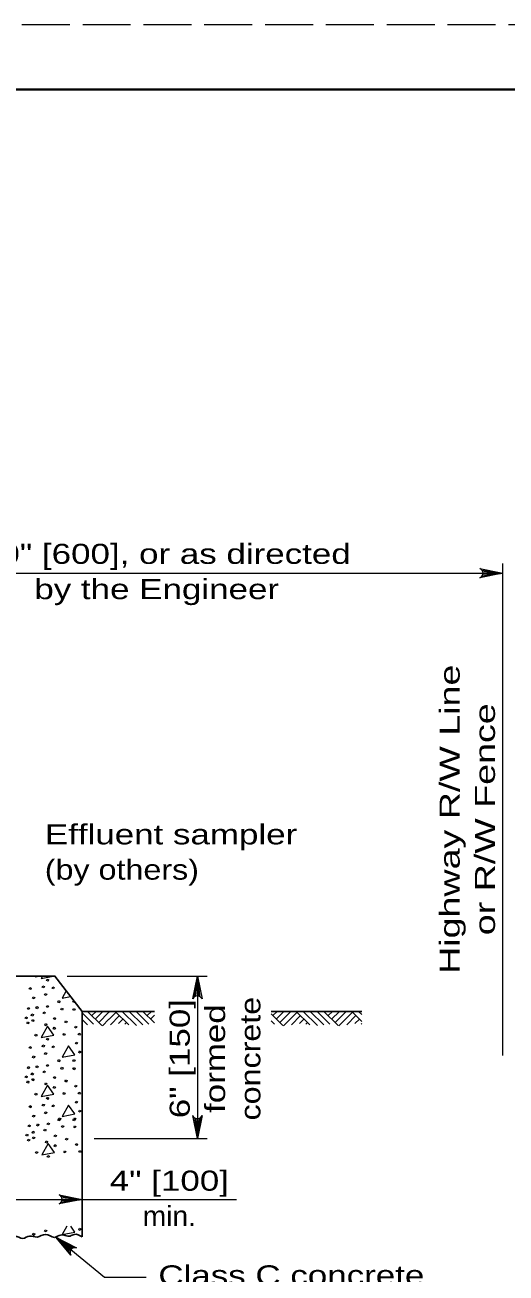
# Model space of a CAD drawing. Extents: x 1083.1 to 1117.1, y 719.4 to 741.4.
# Drawn here: x 1104.03 to 1107.77, y 731.66 to 741.35 of the extents above; entities that cross this region are included whole.
import ezdxf
from ezdxf.enums import TextEntityAlignment as Align

# ---------------------------------------------------------------- set-up
doc = ezdxf.new("R2010")
doc.units = 0
doc.header["$LTSCALE"] = 0.062
doc.linetypes.add('LONG_DASHED', pattern=[7.5, 6, -1.5])
doc.layers.add('1', color=7, linetype='Continuous', lineweight=13)

msp = doc.modelspace()

# ---------------------------------------------------------------- linework, layer by layer
at = {"layer": '1', "lineweight": 25}
for p, q in [((1085.12642, 740.85408), (1116.62642, 740.85408)), ((1105.03925, 733.6935), (1104.47725, 733.6935)), ((1106.63592, 733.6935), (1105.94508, 733.6935)), ((1106.64933, 733.6935), (1106.63592, 733.6935))]:
    msp.add_line(p, q, dxfattribs=at)
at = {"layer": '1'}
for p, q in [((1107.74417, 733.35042), (1107.74417, 737.17217)), ((1102.07067, 737.09617), (1107.74417, 737.09617)), ((1107.58108, 737.12117), (1107.74417, 737.09617)), ((1107.583, 737.07367), (1107.74417, 737.09617)), ((1107.58725, 737.11067), (1107.74417, 737.09617)), ((1107.58842, 737.08483), (1107.74417, 737.09617)), ((1107.59008, 737.09617), (1107.74417, 737.09617)), ((1104.36233, 733.96767), (1105.44883, 733.96767)), ((1105.348, 733.80458), (1105.37292, 733.96767)), ((1105.35842, 733.81075), (1105.37292, 733.96767)), ((1105.37292, 733.81367), (1105.37292, 733.96767)), ((1105.38425, 733.812), (1105.37292, 733.96767)), ((1105.39542, 733.8065), (1105.37292, 733.96767)), ((1104.41192, 733.77775), (1104.41317, 733.77725)), ((1104.47725, 733.68325), (1104.56525, 733.59533)), ((1104.52067, 733.6935), (1104.63067, 733.58358)), ((1104.52658, 733.68758), (1104.5325, 733.6935)), ((1104.55342, 733.66075), (1104.58617, 733.6935)), ((1104.58025, 733.63392), (1104.63992, 733.6935)), ((1104.58283, 733.6935), (1104.5835, 733.69292)), ((1104.60717, 733.60708), (1104.68658, 733.68658)), ((1104.68767, 733.68767), (1104.69358, 733.6935)), ((1104.68767, 733.63383), (1104.74142, 733.68758)), ((1104.69708, 733.58967), (1104.76825, 733.66075)), ((1104.7355, 733.6935), (1104.83967, 733.58942)), ((1104.78917, 733.6935), (1104.90008, 733.58267)), ((1104.84283, 733.6935), (1104.94833, 733.58808)), ((1104.89667, 733.6935), (1104.99492, 733.59533)), ((1104.95033, 733.6935), (1105.03925, 733.60467)), ((1104.95625, 733.68758), (1104.96217, 733.6935)), ((1104.98317, 733.66075), (1105.01592, 733.6935)), ((1105.01, 733.63392), (1105.03925, 733.66325)), ((1105.94508, 733.67408), (1106.03567, 733.58358)), ((1105.95842, 733.66075), (1105.99125, 733.6935)), ((1105.98525, 733.63392), (1106.04483, 733.6935)), ((1106.01208, 733.60708), (1106.09158, 733.68658)), ((1106.09267, 733.68767), (1106.0985, 733.6935)), ((1106.09267, 733.63383), (1106.1465, 733.68758)), ((1106.10217, 733.58967), (1106.17325, 733.66075)), ((1106.14042, 733.6935), (1106.24458, 733.58942)), ((1106.19417, 733.6935), (1106.305, 733.58267)), ((1106.24783, 733.6935), (1106.35342, 733.58808)), ((1106.30167, 733.6935), (1106.39992, 733.59533)), ((1106.35533, 733.6935), (1106.46533, 733.58358)), ((1106.36133, 733.68758), (1106.36725, 733.6935)), ((1106.38808, 733.66075), (1106.42092, 733.6935)), ((1106.41492, 733.63392), (1106.47458, 733.6935)), ((1106.44175, 733.60708), (1106.52133, 733.68658)), ((1106.52242, 733.68767), (1106.52825, 733.6935)), ((1106.52242, 733.63383), (1106.57617, 733.68758)), ((1106.53183, 733.58967), (1106.603, 733.66075)), ((1106.57017, 733.6935), (1106.64933, 733.61442)), ((1106.62383, 733.6935), (1106.64933, 733.66808)), ((1104.47725, 733.62992), (1104.48125, 733.63392)), ((1104.47725, 733.6295), (1104.51867, 733.58808)), ((1104.63625, 733.58233), (1104.68658, 733.63275)), ((1104.75967, 733.5985), (1104.79517, 733.63392)), ((1104.80942, 733.5945), (1104.822, 733.60708)), ((1105.03683, 733.60708), (1105.03925, 733.6095)), ((1105.94508, 733.62042), (1105.97017, 733.59533)), ((1106.04125, 733.58233), (1106.09158, 733.63275)), ((1106.16475, 733.5985), (1106.20008, 733.63392)), ((1106.21433, 733.5945), (1106.22692, 733.60708)), ((1106.47092, 733.58233), (1106.52133, 733.63275)), ((1106.59442, 733.5985), (1106.62975, 733.63392)), ((1106.644, 733.5945), (1106.64933, 733.59975)), ((1105.35033, 732.86808), (1105.37292, 732.70692)), ((1105.39783, 732.86992), (1105.37292, 732.70692)), ((1105.3615, 732.86258), (1105.37292, 732.70692)), ((1105.38742, 732.86375), (1105.37292, 732.70692)), ((1105.37292, 732.86092), (1105.37292, 732.70692)), ((1104.57217, 732.70692), (1105.44883, 732.70692)), ((1103.53142, 732.23342), (1105.67708, 732.23342)), ((1104.31417, 732.25833), (1104.47725, 732.23342)), ((1104.316, 732.21083), (1104.47725, 732.23342)), ((1104.32033, 732.24783), (1104.47725, 732.23342)), ((1104.3215, 732.222), (1104.47725, 732.23342)), ((1104.32317, 732.23342), (1104.47725, 732.23342)), ((1104.3935, 731.844), (1104.27367, 731.94075)), ((1104.38667, 731.83092), (1104.27367, 731.94075)), ((1104.38492, 731.819), (1104.27367, 731.94075)), ((1104.402, 731.85183), (1104.27367, 731.94075)), ((1104.41325, 731.85708), (1104.27367, 731.94075))]:
    msp.add_line(p, q, dxfattribs=at)
at = {"layer": '1', "linetype": 'LONG_DASHED'}
msp.add_lwpolyline([(1083.12642, 719.35408), (1117.12642, 719.35408), (1117.12642, 741.35408), (1083.12642, 741.35408)], close=True, dxfattribs=at)
at = {"layer": '1', "lineweight": 40}
msp.add_lwpolyline([(1085.12642, 740.85408), (1116.62642, 740.85408), (1116.62642, 719.85408), (1085.12642, 719.85408)], close=True, dxfattribs=at)
msp.add_lwpolyline([(1085.12642, 740.85408), (1116.62642, 740.85408), (1116.62642, 719.85408), (1085.12642, 719.85408)], close=True, dxfattribs=at)
at = {"layer": '1'}
for points in [[(1107.56617, 737.13183), (1107.74417, 737.09617), (1107.56617, 737.06058)], [(1104.12633, 733.96767), (1104.12233, 733.95967), (1104.1105, 733.96442), (1104.11217, 733.96767)], [(1104.1705, 733.96767), (1104.16033, 733.94942), (1104.254, 733.96767)], [(1105.33725, 733.78967), (1105.37292, 733.96767), (1105.4085, 733.78967)], [(1105.37292, 733.96767), (1105.37292, 733.56408), (1105.37292, 732.70692)], [(1104.35525, 733.85292), (1104.32333, 733.79592), (1104.38908, 733.80875)], [(1104.42092, 733.76708), (1104.41825, 733.76192), (1104.40642, 733.76667), (1104.41192, 733.77775)], [(1105.4085, 732.88492), (1105.37292, 732.70692), (1105.33725, 732.88492)], [(1104.29917, 732.269), (1104.47725, 732.23342), (1104.29917, 732.19775)], [(1104.359, 732.02417), (1104.32333, 731.96033), (1104.42067, 731.97925), (1104.38917, 732.02417)], [(1104.38983, 731.80125), (1104.27367, 731.94075), (1104.4345, 731.85667)], [(1104.27367, 731.94075), (1104.65108, 731.62875), (1104.97592, 731.62875)]]:
    msp.add_lwpolyline(points, dxfattribs=at)
at = {"layer": '1', "lineweight": 25}
for points in [[(1103.9085, 733.15417), (1103.94058, 733.96767), (1104.26742, 733.96767), (1104.47725, 733.6935)], [(1104.47725, 733.6935), (1104.47725, 732.02417), (1104.47725, 731.94125)]]:
    msp.add_lwpolyline(points, dxfattribs=at)
at = {"layer": '1'}
for points in [[(1104.20625, 733.94467), (1104.21808, 733.93992), (1104.21333, 733.928), (1104.2015, 733.93358)], [(1104.07167, 733.87975), (1104.08358, 733.87425), (1104.07883, 733.86317), (1104.06692, 733.86867)], [(1104.17375, 733.89167), (1104.18567, 733.88692), (1104.18092, 733.875), (1104.169, 733.88058)], [(1104.24975, 733.88533), (1104.26158, 733.87975), (1104.25683, 733.86867), (1104.245, 733.87342)], [(1104.09858, 733.80617), (1104.1105, 733.80142), (1104.10575, 733.78958), (1104.09383, 733.79508)], [(1104.192, 733.83233), (1104.20383, 733.82758), (1104.19833, 733.8165), (1104.18642, 733.82125)], [(1104.294, 733.77775), (1104.30592, 733.77217), (1104.30117, 733.76108), (1104.28933, 733.76583)], [(1104.04083, 733.65192), (1104.05267, 733.64717), (1104.04792, 733.63608), (1104.03608, 733.64083)], [(1104.05825, 733.72392), (1104.07008, 733.71833), (1104.06533, 733.70733), (1104.0535, 733.712)], [(1104.08833, 733.67408), (1104.10017, 733.6685), (1104.09542, 733.65742), (1104.08358, 733.66217)], [(1104.1255, 733.73025), (1104.13733, 733.7255), (1104.13183, 733.71358), (1104.12, 733.71917)], [(1104.18008, 733.69067), (1104.192, 733.68517), (1104.18725, 733.67408), (1104.17533, 733.67958)], [(1104.20625, 733.73975), (1104.21808, 733.73417), (1104.21258, 733.72308), (1104.20067, 733.72867)], [(1104.26083, 733.64717), (1104.27267, 733.64158), (1104.26792, 733.63058), (1104.25608, 733.63533)], [(1104.31775, 733.71833), (1104.32967, 733.71283), (1104.32492, 733.70175), (1104.313, 733.70733)], [(1104.41192, 733.716), (1104.42383, 733.71125), (1104.41825, 733.69942), (1104.40642, 733.70492)], [(1104.0535, 733.61233), (1104.06533, 733.60683), (1104.06058, 733.59575), (1104.04875, 733.60125)], [(1104.09225, 733.63058), (1104.10417, 733.625), (1104.09942, 733.61392), (1104.0875, 733.6195)], [(1104.20942, 733.57833), (1104.16033, 733.4905), (1104.25767, 733.5095)], [(1104.19275, 733.59808), (1104.20467, 733.59333), (1104.19992, 733.5815), (1104.188, 733.587)], [(1104.26, 733.56958), (1104.27192, 733.56408), (1104.26633, 733.553), (1104.2545, 733.55775)], [(1104.34942, 733.62025), (1104.36133, 733.6155), (1104.35575, 733.60367), (1104.34392, 733.60917)], [(1104.42542, 733.57908), (1104.43725, 733.57433), (1104.4325, 733.56333), (1104.42067, 733.568)], [(1104.116, 733.51658), (1104.12783, 733.51183), (1104.12233, 733.50075), (1104.1105, 733.5055)], [(1104.20625, 733.48575), (1104.21808, 733.481), (1104.21333, 733.46917), (1104.2015, 733.47467)], [(1104.33442, 733.52133), (1104.34625, 733.51658), (1104.3415, 733.5055), (1104.32967, 733.51025)], [(1104.43092, 733.45408), (1104.44283, 733.44933), (1104.43808, 733.43825), (1104.42617, 733.443)], [(1104.45233, 733.5245), (1104.46417, 733.51975), (1104.45867, 733.50867), (1104.44675, 733.51342)], [(1104.07167, 733.42083), (1104.08358, 733.41533), (1104.07883, 733.40425), (1104.06692, 733.40983)], [(1104.17375, 733.43275), (1104.18567, 733.428), (1104.18092, 733.41617), (1104.169, 733.42167)], [(1104.192, 733.37342), (1104.20383, 733.36867), (1104.19833, 733.35758), (1104.18642, 733.36233)], [(1104.24975, 733.42642), (1104.26158, 733.42083), (1104.25683, 733.40983), (1104.245, 733.4145)], [(1104.37242, 733.42483), (1104.32333, 733.337), (1104.42067, 733.356)], [(1104.45708, 733.38608), (1104.46892, 733.3805), (1104.46342, 733.36942), (1104.4515, 733.37417)], [(1104.05825, 733.265), (1104.07008, 733.2595), (1104.06533, 733.24842), (1104.0535, 733.25317)], [(1104.09858, 733.34725), (1104.1105, 733.34258), (1104.10575, 733.33067), (1104.09383, 733.33625)], [(1104.1255, 733.27133), (1104.13733, 733.26658), (1104.13183, 733.25475), (1104.12, 733.26025)], [(1104.20625, 733.28083), (1104.21808, 733.27525), (1104.21258, 733.26425), (1104.20067, 733.26975)], [(1104.294, 733.31883), (1104.30592, 733.31325), (1104.30117, 733.30217), (1104.28933, 733.30692)], [(1104.31775, 733.2595), (1104.32967, 733.25392), (1104.32492, 733.24283), (1104.313, 733.24842)], [(1104.41192, 733.31883), (1104.42383, 733.31408), (1104.41825, 733.303), (1104.40642, 733.30775)], [(1104.41192, 733.25708), (1104.42383, 733.25233), (1104.41825, 733.2405), (1104.40642, 733.246)], [(1104.04083, 733.193), (1104.05267, 733.18825), (1104.04792, 733.17717), (1104.03608, 733.18192)], [(1104.08833, 733.21517), (1104.10017, 733.20958), (1104.09542, 733.19858), (1104.08358, 733.20325)], [(1104.09225, 733.17167), (1104.10417, 733.16608), (1104.09942, 733.155), (1104.0875, 733.16058)], [(1104.18008, 733.23175), (1104.192, 733.22625), (1104.18725, 733.21517), (1104.17533, 733.22067)], [(1104.26083, 733.18825), (1104.27267, 733.18275), (1104.26792, 733.17167), (1104.25608, 733.17642)], [(1104.34942, 733.16133), (1104.36133, 733.15658), (1104.35575, 733.14475), (1104.34392, 733.15025)], [(1104.0535, 733.15342), (1104.06533, 733.14792), (1104.06058, 733.13683), (1104.04875, 733.14233)], [(1104.20942, 733.11942), (1104.16033, 733.03158), (1104.25767, 733.05058)], [(1104.19275, 733.13917), (1104.20467, 733.13442), (1104.19992, 733.12258), (1104.188, 733.12808)], [(1104.26, 733.11075), (1104.27192, 733.10517), (1104.26633, 733.09408), (1104.2545, 733.09883)], [(1104.33442, 733.06242), (1104.34625, 733.05767), (1104.3415, 733.04667), (1104.32967, 733.05142)], [(1104.42542, 733.12025), (1104.43725, 733.1155), (1104.4325, 733.10442), (1104.42067, 733.10917)], [(1104.45233, 733.06558), (1104.46417, 733.06083), (1104.45867, 733.04983), (1104.44675, 733.0545)], [(1104.116, 733.05767), (1104.12783, 733.053), (1104.12233, 733.04192), (1104.1105, 733.04667)], [(1104.17375, 732.97383), (1104.18567, 732.96908), (1104.18092, 732.95725), (1104.169, 732.96275)], [(1104.20625, 733.02683), (1104.21808, 733.02208), (1104.21333, 733.01025), (1104.2015, 733.01575)], [(1104.24975, 732.9675), (1104.26158, 732.962), (1104.25683, 732.95092), (1104.245, 732.95567)], [(1104.37242, 732.96592), (1104.32333, 732.87808), (1104.42067, 732.89708)], [(1104.43092, 732.99517), (1104.44283, 732.99042), (1104.43808, 732.97942), (1104.42617, 732.98408)], [(1104.07167, 732.962), (1104.08358, 732.95642), (1104.07883, 732.94533), (1104.06692, 732.95092)], [(1104.09858, 732.88842), (1104.1105, 732.88367), (1104.10575, 732.87175), (1104.09383, 732.87733)], [(1104.192, 732.9145), (1104.20383, 732.90975), (1104.19833, 732.89867), (1104.18642, 732.90342)], [(1104.45708, 732.92717), (1104.46892, 732.92158), (1104.46342, 732.9105), (1104.4515, 732.91525)], [(1104.06425, 732.81258), (1104.07608, 732.80708), (1104.07133, 732.796), (1104.0595, 732.80075)], [(1104.1315, 732.81892), (1104.14333, 732.81417), (1104.13783, 732.80233), (1104.12592, 732.80783)], [(1104.18608, 732.77942), (1104.19792, 732.77383), (1104.19317, 732.76275), (1104.18133, 732.76833)], [(1104.21217, 732.82842), (1104.22408, 732.82292), (1104.2185, 732.81183), (1104.20667, 732.81733)], [(1104.294, 732.85992), (1104.30592, 732.85433), (1104.30117, 732.84325), (1104.28933, 732.848)], [(1104.3, 732.86642), (1104.31192, 732.86083), (1104.30717, 732.84983), (1104.29525, 732.85458)], [(1104.32375, 732.80708), (1104.33567, 732.8015), (1104.33092, 732.7905), (1104.319, 732.796)], [(1104.41192, 732.85992), (1104.42383, 732.85517), (1104.41825, 732.84408), (1104.40642, 732.84883)], [(1104.41792, 732.86642), (1104.42983, 732.86167), (1104.42425, 732.85058), (1104.41242, 732.85533)], [(1104.41792, 732.80467), (1104.42983, 732.79992), (1104.42425, 732.78808), (1104.41242, 732.79358)], [(1104.04683, 732.74058), (1104.05867, 732.73583), (1104.05392, 732.72475), (1104.04208, 732.7295)], [(1104.0595, 732.70108), (1104.07133, 732.6955), (1104.06658, 732.68442), (1104.05475, 732.69)], [(1104.09433, 732.76275), (1104.10617, 732.75725), (1104.10142, 732.74617), (1104.08958, 732.75092)], [(1104.09825, 732.71925), (1104.11008, 732.71367), (1104.10533, 732.70267), (1104.0935, 732.70817)], [(1104.19875, 732.68683), (1104.21058, 732.68208), (1104.20583, 732.67017), (1104.194, 732.67575)], [(1104.26683, 732.73583), (1104.27867, 732.73033), (1104.27392, 732.71925), (1104.26208, 732.724)], [(1104.35542, 732.709), (1104.36725, 732.70425), (1104.36175, 732.69233), (1104.34992, 732.69792)], [(1104.122, 732.60533), (1104.13383, 732.60058), (1104.12833, 732.5895), (1104.11642, 732.59425)], [(1104.21533, 732.667), (1104.16633, 732.57917), (1104.26367, 732.59817)], [(1104.266, 732.65833), (1104.27783, 732.65275), (1104.27233, 732.64175), (1104.2605, 732.64642)], [(1104.34042, 732.61008), (1104.35225, 732.60533), (1104.3475, 732.59425), (1104.33567, 732.599)], [(1104.43142, 732.66783), (1104.44325, 732.66308), (1104.4385, 732.652), (1104.42667, 732.65675)], [(1104.45825, 732.61325), (1104.47017, 732.6085), (1104.46458, 732.59742), (1104.45275, 732.60217)], [(1104.21217, 732.57442), (1104.22408, 732.56967), (1104.21933, 732.55783), (1104.20742, 732.56342)], [(1104.192, 731.99667), (1104.20383, 731.99192), (1104.19833, 731.98083), (1104.18642, 731.98558)], [(1104.45708, 732.00933), (1104.46892, 732.00383), (1104.46342, 731.99275), (1104.4515, 731.9975)], [(1104.09858, 731.97058), (1104.1105, 731.96583), (1104.10575, 731.954), (1104.09383, 731.9595)]]:
    msp.add_lwpolyline(points, close=True, dxfattribs=at)
for centre, major_axis, start_param, end_param in [((1107.55167, 737.09621), (0.03843, 0), 5.0978942, 7.4685073), ((1105.37289, 733.77521), (0.03843, 0), 0.3855052, 2.7561184), ((1105.37289, 732.89936), (-0.03843, 0), 0.3855052, 2.7561184), ((1104.28474, 732.23337), (0.03843, 0), 5.0978942, 7.4685073), ((1104.42342, 731.81989), (0.03742, 0.00872), 1.0483626, 3.4189757)]:
    msp.add_ellipse(centre, major_axis=major_axis, ratio=0.999895, start_param=start_param, end_param=end_param, dxfattribs=at)
at = {"layer": '1', "lineweight": 25}
msp.add_spline([(1104.47725, 731.94125), (1104.41808, 731.96192), (1104.38417, 731.94892), (1104.31108, 731.95675), (1104.264, 731.9385), (1104.1935, 731.96192), (1104.12817, 731.94108), (1104.07075, 731.94892), (1104.0185, 731.93058), (1103.95583, 731.94633), (1103.91408, 731.93058), (1103.86967, 731.94367), (1103.82792, 731.93325), (1103.79392, 731.9385), (1103.74958, 731.928), (1103.73392, 731.93058), (1103.6895, 731.94367), (1103.64775, 731.928), (1103.62683, 731.93325), (1103.5955, 731.9385), (1103.572, 731.93058), (1103.53133, 731.94125)], degree=3, dxfattribs=at)

# ---------------------------------------------------------------- texts
at = {"layer": '1'}
for s, width, p in [('2\'-0" [600], or as directed', 1.3, (1105.05692, 737.16875)), ('by the Engineer', 1.3, (1105.05687, 736.89475)), ('4" [100]', 1.3, (1105.15492, 732.30067)), ('min.', 1.05, (1105.15492, 732.02667))]:
    msp.add_text(s, height=0.156, dxfattribs=dict(at, width=width)).set_placement(p, align=Align.CENTER)
for s, width, p in [('Highway R/W Line', 1.4, (1107.40858, 735.1855)), ('or R/W Fence', 1.4, (1107.68258, 735.18554)), ('6" [150]', 1.3, (1105.3135, 733.32642)), ('concrete', 1.2, (1105.8615, 733.32642)), ('formed', 1.3, (1105.5875, 733.32642))]:
    msp.add_text(s, height=0.156, rotation=90, dxfattribs=dict(at, width=width)).set_placement(p, align=Align.CENTER)
for s, width, p in [('Effluent sampler', 1.3, (1104.18833, 734.99033)), ('(by others)', 1.2, (1104.18833, 734.71633)), ('Class C concrete', 1.3, (1105.06958, 731.565))]:
    msp.add_text(s, height=0.156, dxfattribs=dict(at, width=width)).set_placement(p)

doc.saveas('drawing.dxf')
